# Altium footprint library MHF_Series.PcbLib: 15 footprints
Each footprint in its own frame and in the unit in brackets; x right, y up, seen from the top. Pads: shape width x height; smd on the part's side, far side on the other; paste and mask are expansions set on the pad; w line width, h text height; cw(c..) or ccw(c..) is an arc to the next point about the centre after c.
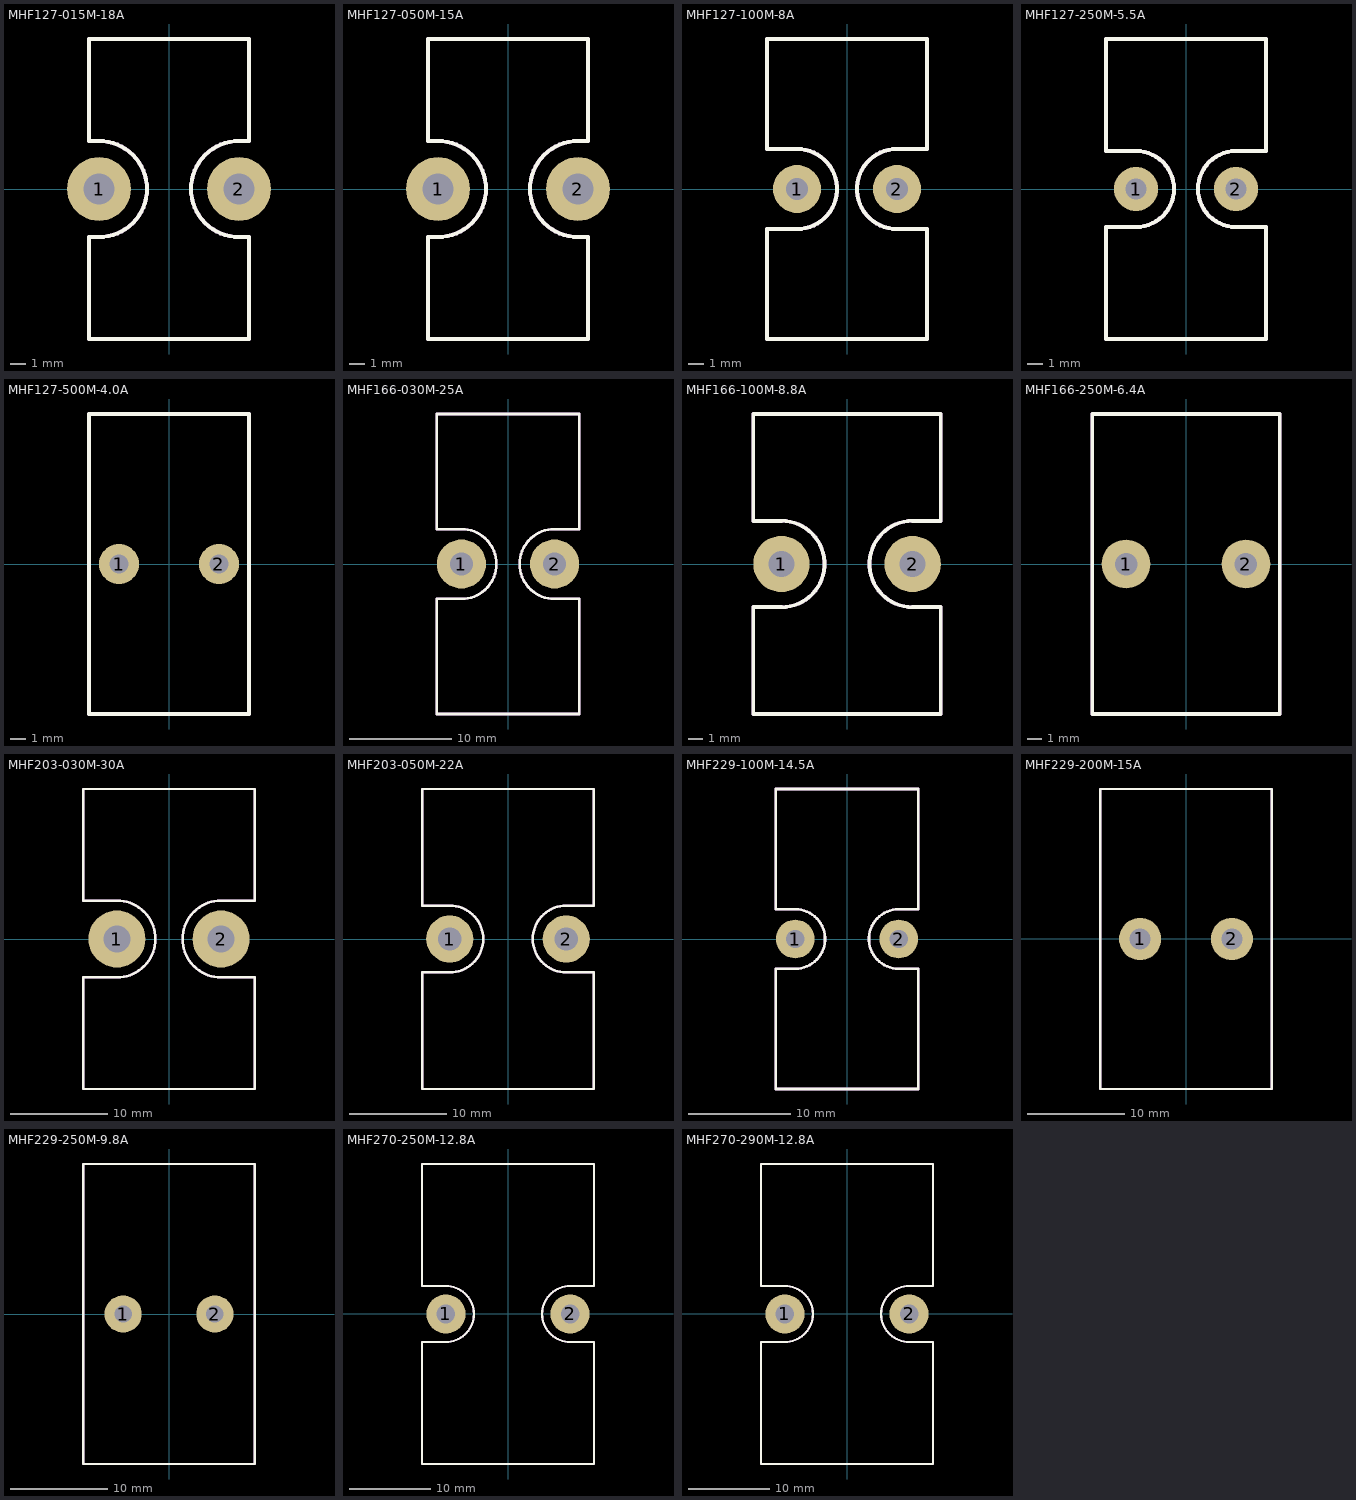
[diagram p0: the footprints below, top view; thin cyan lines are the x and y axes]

## MHF127-015M-18A [mil]
pads (2):
  round 160 hole 77: 1(-175,0) 2(175,0)
Top Overlay:
  lines w10: -200,-375 200,-375 200,-120 175,-120 cw(c175,0) 175,120 200,120 200,375 -200,375 -200,120 -175,120 cw(c-175,0) -175,-120 -200,-120 -200,-375
Mechanical 29:
  lines w10: -200,-375 200,-375 200,-120 175,-120 cw(c175,0) 175,120 200,120 200,375 -200,375 -200,120 -175,120 cw(c-175,0) -175,-120 -200,-120 -200,-375
  text "'.Designator'" at -1750,-64.83 h400

## MHF127-050M-15A [mil]
pads (2):
  round 160 hole 77: 1(-175,0) 2(175,0)
Top Overlay:
  lines w10: -200,-375 200,-375 200,-120 175,-120 cw(c175,0) 175,120 200,120 200,375 -200,375 -200,120 -175,120 cw(c-175,0) -175,-120 -200,-120 -200,-375
Mechanical 29:
  lines w10: -200,-375 200,-375 200,-120 175,-120 cw(c175,0) 175,120 200,120 200,375 -200,375 -200,120 -175,120 cw(c-175,0) -175,-120 -200,-120 -200,-375
  text "'.Designator'" at -1750,-64.83 h400

## MHF127-100M-8A [mil]
pads (2):
  round 120 hole 56: 1(-125,0) 2(125,0)
Top Overlay:
  lines w10: -200,-375 -200,-100 -125,-100 ccw(c-125,0) -125,100 -200,100 -200,375 200,375 200,100 125,100 ccw(c125,0) 125,-100 200,-100 200,-375 -200,-375
Mechanical 29:
  lines w10: -200,-375 -200,-100 -125,-100 ccw(c-125,0) -125,100 -200,100 -200,375 200,375 200,100 125,100 ccw(c125,0) 125,-100 200,-100 200,-375 -200,-375
  text "'.Designator'" at -1750,-64.83 h400

## MHF127-250M-5.5A [mil]
pads (2):
  round 110 hole 52: 1(-125,0) 2(125,0)
Top Overlay:
  lines w10: -200,-375 -200,-95 -125,-95 ccw(c-125,0) -125,95 -200,95 -200,375 200,375 200,95 125,95 ccw(c125,0) 125,-95 200,-95 200,-375 -200,-375
Mechanical 29:
  lines w10: -200,-375 -200,-95 -125,-95 ccw(c-125,0) -125,95 -200,95 -200,375 200,375 200,95 125,95 ccw(c125,0) 125,-95 200,-95 200,-375 -200,-375
  text "'.Designator'" at -1750,-64.83 h400

## MHF127-500M-4.0A [mil]
pads (2):
  round 100 hole 48: 1(-125,0) 2(125,0)
Top Overlay:
  lines w10: -200,-375 -200,145 -200,375 200,375 200,145 200,-375 -200,-375
Mechanical 29:
  lines w10: -200,-375 -200,145 -200,375 200,375 200,145 200,-375 -200,-375
  text "'.Designator'" at -1750,-64.83 h400

## MHF166-030M-25A [mil]
pads (2):
  round 190 hole 90: 1(-180,0) 2(180,0)
Top Overlay:
  lines w10: -275,-580 275,-580 275,-135 180,-135 cw(c180,0) 180,135 275,135 275,580 -275,580 -275,135 -180,135 cw(c-180,0) -180,-135 -275,-135 -275,-580
Mechanical 29:
  lines w10: -275,-580 275,-580 275,-135 180,-135 cw(c180,0) 180,135 275,135 275,580 -275,580 -275,135 -180,135 cw(c-180,0) -180,-135 -275,-135 -275,-580
  text "'.Designator'" at -1750,-64.83 h400

## MHF166-100M-8.8A [mil]
pads (2):
  round 150 hole 70: 1(-175,0) 2(175,0)
Top Overlay:
  lines w10: -250,-400 250,-400 250,-115 175,-115 cw(c175,0) 175,115 250,115 250,400 -250,400 -250,115 -175,115 cw(c-175,0) -175,-115 -250,-115 -250,-400
Mechanical 29:
  lines w10: -250,-400 250,-400 250,-115 175,-115 cw(c175,0) 175,115 250,115 250,400 -250,400 -250,115 -175,115 cw(c-175,0) -175,-115 -250,-115 -250,-400
  text "'.Designator'" at -1750,-64.83 h400

## MHF166-250M-6.4A [mil]
pads (2):
  round 130 hole 60: 1(-160,0) 2(160,0)
Top Overlay:
  lines w10: -250,-400 250,-400 250,145 250,400 -250,400 -250,145 -250,-400
Mechanical 29:
  lines w10: -250,-400 250,-400 250,145 250,400 -250,400 -250,145 -250,-400
  text "'.Designator'" at -1750,-64.83 h400

## MHF203-030M-30A [mil]
pads (2):
  round 230 hole 110: 1(-210,0) 2(210,0)
Top Overlay:
  lines w10: -345,-605 -345,-155 -210,-155 ccw(c-210,0) -210,155 -345,155 -345,605 345,605 345,155 210,155 ccw(c210,0) 210,-155 345,-155 345,-605 -345,-605
Mechanical 29:
  lines w10: -345,-605 -345,-155 -210,-155 ccw(c-210,0) -210,155 -345,155 -345,605 345,605 345,155 210,155 ccw(c210,0) 210,-155 345,-155 345,-605 -345,-605
  text "'.Designator'" at -1750,-64.83 h400

## MHF203-050M-22A [mil]
pads (2):
  round 190 hole 93: 1(-235,0) 2(235,0)
Top Overlay:
  lines w10: -345,-605 -345,-135 -235,-135 ccw(c-235,0) -235,135 -345,135 -345,605 345,605 345,135 235,135 ccw(c235,0) 235,-135 345,-135 345,-605 -345,-605
Mechanical 29:
  lines w10: -345,-605 -345,-135 -235,-135 ccw(c-235,0) -235,135 -345,135 -345,605 345,605 345,135 235,135 ccw(c235,0) 235,-135 345,-135 345,-605 -345,-605
  text "'.Designator'" at -1750,-64.83 h400

## MHF229-100M-14.5A [mil]
pads (2):
  round 150 hole 71: 1(-200,0) 2(200,0)
Top Overlay:
  lines w10: -275,-580 275,-580 275,-115 200,-115 cw(c200,0) 200,115 275,115 275,580 -275,580 -275,115 -200,115 cw(c-200,0) -200,-115 -275,-115 -275,-580
Mechanical 29:
  lines w10: -275,-580 275,-580 275,-115 200,-115 cw(c200,0) 200,115 275,115 275,580 -275,580 -275,115 -200,115 cw(c-200,0) -200,-115 -275,-115 -275,-580
  text "'.Designator'" at -1750,-64.83 h400

## MHF229-200M-15A [mil]
pads (2):
  round 170 hole 84: 1(-185,0) 2(185,0)
Top Overlay:
  lines w10: -345,-605 345,-605 345,145 345,605 -345,605 -345,145 -345,-605
Mechanical 29:
  lines w10: -345,-605 345,-605 345,145 345,605 -345,605 -345,145 -345,-605
  text "'.Designator'" at -1750,-64.83 h400

## MHF229-250M-9.8A [mil]
pads (2):
  round 150 hole 70: 1(-185,0) 2(185,0)
Top Overlay:
  lines w10: -345,-605 -345,135 -345,605 345,605 345,135 345,-605 -345,-605
Mechanical 29:
  lines w10: -345,-605 -345,135 -345,605 345,605 345,135 345,-605 -345,-605
  text "'.Designator'" at -1750,-64.83 h400

## MHF270-250M-12.8A [mil]
pads (2):
  round 190 hole 90: 1(-300,0) 2(300,0)
Top Overlay:
  lines w10: -415,-725 -415,-135 -300,-135 ccw(c-300,0) -300,135 -415,135 -415,725 415,725 415,135 300,135 ccw(c300,0) 300,-135 415,-135 415,-725 -415,-725
Mechanical 29:
  lines w10: -415,-725 -415,-135 -300,-135 ccw(c-300,0) -300,135 -415,135 -415,725 415,725 415,135 300,135 ccw(c300,0) 300,-135 415,-135 415,-725 -415,-725
  text "'.Designator'" at -1750,-64.83 h400

## MHF270-290M-12.8A [mil]
pads (2):
  round 190 hole 90: 1(-300,0) 2(300,0)
Top Overlay:
  lines w10: -415,-725 415,-725 415,-135 300,-135 cw(c300,0) 300,135 415,135 415,725 -415,725 -415,135 -300,135 cw(c-300,0) -300,-135 -415,-135 -415,-725
Mechanical 29:
  lines w10: -415,-725 415,-725 415,-135 300,-135 cw(c300,0) 300,135 415,135 415,725 -415,725 -415,135 -300,135 cw(c-300,0) -300,-135 -415,-135 -415,-725
  text "'.Designator'" at -1750,-64.83 h400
